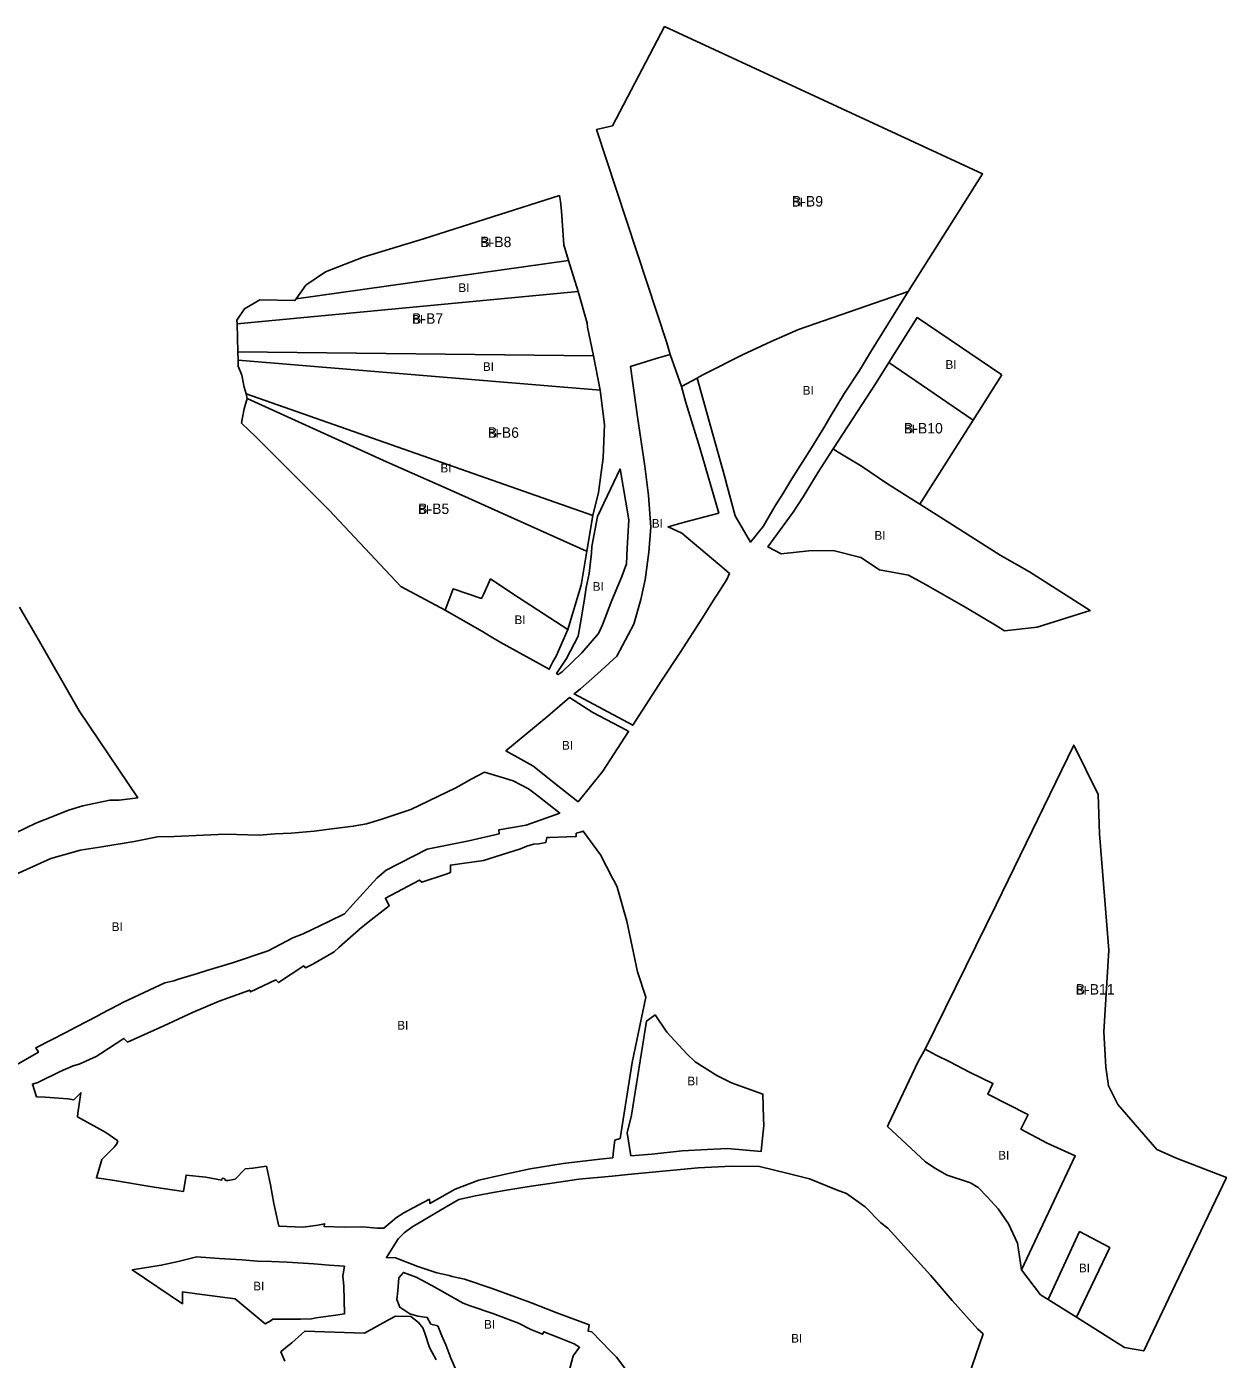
# Model space of a CAD drawing. Extents: x -532081 to -530154, y -1179372 to -1177675.
# Drawn here: x -530843 to -530154, y -1178440 to -1177675 of the extents above; entities that cross this region are included whole.
import ezdxf

# ---------------------------------------------------------------- set-up
doc = ezdxf.new("R2010")
doc.units = 0
for name, color, linetype in [('90040013', 7, 'Continuous'), ('90040023', 7, 'Continuous'), ('ID_navrh', 7, 'Continuous')]:
    doc.layers.add(name, color=color, linetype=linetype)

msp = doc.modelspace()

# ---------------------------------------------------------------- linework, layer by layer
at = {"layer": '90040013'}
for points in [[(-530526.69, -1177827.31), (-530722.54, -1177845.73), (-530722.6, -1177843.68), (-530718.37, -1177837.23), (-530709.55, -1177832.07), (-530689.34, -1177832.44), (-530688.56, -1177831.34), (-530532.17, -1177809.38)], [(-530420.51, -1177962.1), (-530427.66, -1177971.09), (-530436.58, -1177955.98), (-530441.05, -1177938.92), (-530442.44, -1177933.89), (-530450.53, -1177905.07), (-530458.33, -1177876.89), (-530457.17, -1177876.17), (-530454.3, -1177874.68), (-530431.86, -1177863.3), (-530415.76, -1177855.88), (-530400.19, -1177849), (-530337.11, -1177827.29), (-530358.71, -1177862.11), (-530365.16, -1177872.5), (-530373.77, -1177885.58), (-530381.89, -1177899.15), (-530385.09, -1177904.58), (-530392.72, -1177916.92), (-530404.03, -1177934.69), (-530409.22, -1177943.28), (-530413.51, -1177950.3)], [(-530283.32, -1177875.02), (-530299.85, -1177901.09), (-530348.29, -1177868.05), (-530332.03, -1177842.16)], [(-530517.77, -1177864.16), (-530514.06, -1177883.77), (-530721.96, -1177866.61), (-530722.09, -1177861.89)], [(-530478.55, -1178050.25), (-530495.32, -1178076.19), (-530529, -1178058.26), (-530527.39, -1178056.99), (-530525.33, -1178055.37), (-530515.59, -1178046.73), (-530504.42, -1178036.64), (-530494.66, -1178018.22), (-530490.7, -1178004.09), (-530488.92, -1177996.27), (-530488.25, -1177992.7), (-530486.02, -1177976.84), (-530484.86, -1177962.56), (-530486.25, -1177944.29), (-530488.45, -1177927.41), (-530489.14, -1177922.4), (-530492.61, -1177899.23), (-530496.53, -1177870.21), (-530481.9, -1177865.72), (-530473.8, -1177863.4), (-530467.3, -1177881.68), (-530464.84, -1177890.96), (-530456.71, -1177916.98), (-530445.9, -1177954.38), (-530465.57, -1177959.62), (-530474.98, -1177962.4), (-530467.09, -1177965.9), (-530442.82, -1177986.45), (-530439.7, -1177989.13), (-530441.26, -1177992.48), (-530447.05, -1178001.63), (-530447.92, -1178002.82), (-530455.3, -1178014.53), (-530468.16, -1178034.39)], [(-530518.2, -1177955.79), (-530521.7, -1177976.32), (-530521.84, -1177976.26), (-530599.09, -1177941.7), (-530636.79, -1177924.96), (-530716.72, -1177888.65), (-530717.29, -1177885.88)], [(-530305.43, -1177965.26), (-530284.27, -1177978.52), (-530267.44, -1177988.17), (-530232.58, -1178010.35), (-530263.11, -1178020), (-530281.81, -1178022), (-530286.1, -1178019.27), (-530304.04, -1178008.7), (-530326.86, -1177995.6), (-530337, -1177990.12), (-530353.57, -1177986.99), (-530364.3, -1177979.95), (-530380.29, -1177975.84), (-530394.13, -1177976.04), (-530410.12, -1177977.8), (-530417.72, -1177973.89), (-530403.28, -1177953.92), (-530397.51, -1177945), (-530388.86, -1177931.01), (-530380.2, -1177917.5), (-530378.27, -1177918.87), (-530363.91, -1177927.5), (-530349.67, -1177937.28), (-530335, -1177946.44), (-530330.45, -1177949.34)], [(-530535.84, -1178045.55), (-530538.18, -1178047.15), (-530539.04, -1178046.51), (-530533.34, -1178037.99), (-530526.74, -1178025.1), (-530525.56, -1178018.51), (-530523.19, -1178005.02), (-530522.14, -1177997.17), (-530520.32, -1177989.19), (-530519.04, -1177977.52), (-530518.82, -1177973.51), (-530515.49, -1177956.39), (-530502.63, -1177929.03), (-530497.53, -1177958.39), (-530498.48, -1177974.59), (-530498.93, -1177983.57), (-530501.67, -1177990.89), (-530507.53, -1178005.02), (-530512.76, -1178018.51), (-530515.07, -1178023.53), (-530524.49, -1178034.66)], [(-530564.12, -1178000.77), (-530532.63, -1178021.21), (-530539.39, -1178036.59), (-530541.13, -1178039.86), (-530543.23, -1178044.06), (-530571.38, -1178028.54), (-530577.55, -1178024.92), (-530581.65, -1178022.35), (-530590.11, -1178017.57), (-530602.97, -1178010.16), (-530598.51, -1177997.98), (-530582.15, -1178003.45), (-530580.91, -1178000.72), (-530576.94, -1177992.26)], [(-530512.53, -1178102.63), (-530526.69, -1178120.12), (-530536.63, -1178112.26), (-530552.77, -1178099.51), (-530568.14, -1178090.84), (-530544, -1178071.07), (-530531.7, -1178060.34), (-530518.29, -1178068.83), (-530498.95, -1178079.05), (-530497.7, -1178079.72)], [(-530505.6, -1178166.34), (-530504.31, -1178169.13), (-530498.75, -1178188.63), (-530492.64, -1178217.79), (-530487.83, -1178232.28), (-530495.59, -1178269.85), (-530502.57, -1178313.36), (-530505.56, -1178314.36), (-530506.31, -1178320.36), (-530506.83, -1178324.53), (-530514.29, -1178325.36), (-530535.23, -1178327.86), (-530554.18, -1178330.86), (-530570.13, -1178334.37), (-530583.63, -1178337.37), (-530597.26, -1178342.58), (-530611.92, -1178350.7), (-530612.1, -1178348.28), (-530618.61, -1178351.63), (-530626.79, -1178356.15), (-530631, -1178358.77), (-530638.26, -1178364.84), (-530642.17, -1178364.84), (-530650.48, -1178364.15), (-530660.87, -1178364.28), (-530672.46, -1178364.02), (-530672.33, -1178362.41), (-530676.14, -1178363.11), (-530684.55, -1178364.36), (-530698.61, -1178363.74), (-530698.94, -1178361.96), (-530701.46, -1178350.73), (-530703.26, -1178340.01), (-530705.74, -1178329.32), (-530713.4, -1178330.41), (-530717.88, -1178330.82), (-530723.69, -1178336.85), (-530727.58, -1178337.48), (-530729.09, -1178337.48), (-530729.96, -1178336.47), (-530731.09, -1178336.22), (-530731.35, -1178337.35), (-530740.56, -1178335.56), (-530751.78, -1178334.47), (-530753.32, -1178343.95), (-530770.16, -1178341.36), (-530794.04, -1178337.4), (-530803.31, -1178336.02), (-530800.22, -1178325.51), (-530793.18, -1178318.44), (-530791.5, -1178316.56), (-530791.05, -1178314.8), (-530797.82, -1178310), (-530801.4, -1178308.03), (-530814.14, -1178301.04), (-530813.97, -1178298.97), (-530812.19, -1178287.22), (-530816.3, -1178291.26), (-530819.74, -1178290.7), (-530832.81, -1178289.76), (-530837.7, -1178289.49), (-530840.12, -1178282.23), (-530836.98, -1178281.32), (-530824.17, -1178274.97), (-530816.66, -1178271.63), (-530813.15, -1178270.75), (-530803.54, -1178266.32), (-530800.84, -1178264.72), (-530787.52, -1178255.98), (-530785.38, -1178258.13), (-530773.91, -1178252.91), (-530764.58, -1178248.76), (-530748.05, -1178241.09), (-530732.85, -1178234.6), (-530715.28, -1178228.28), (-530714.78, -1178229.28), (-530700.19, -1178222.29), (-530698.7, -1178223.96), (-530684.28, -1178214.31), (-530683.28, -1178215.48), (-530679.04, -1178213.37), (-530666.8, -1178206.33), (-530663.9, -1178203.53), (-530651.18, -1178192.35), (-530645.46, -1178187.88), (-530635.19, -1178179.84), (-530637.33, -1178175.53), (-530617.69, -1178165.13), (-530616.35, -1178166.36), (-530602.55, -1178161.64), (-530599.89, -1178160.73), (-530600.01, -1178156.45), (-530581.1, -1178153.88), (-530559.81, -1178147.13), (-530556.2, -1178145.56), (-530552.4, -1178144.5), (-530549.29, -1178144.3), (-530545.19, -1178143.44), (-530544.68, -1178140.71), (-530542.9, -1178140.64), (-530533.15, -1178140.29), (-530527.86, -1178140.1), (-530527.74, -1178138.2), (-530525.6, -1178137.56), (-530523.75, -1178137), (-530513.75, -1178150.56), (-530506.9, -1178163.93)], [(-530421.18, -1178316.94), (-530421.63, -1178320.96), (-530440.96, -1178319.17), (-530452.52, -1178319.84), (-530466.92, -1178320.61), (-530484.38, -1178322.36), (-530496.34, -1178323.36), (-530498.58, -1178310.11), (-530496.09, -1178300.11), (-530487.33, -1178246.05), (-530482.46, -1178242.5), (-530475.79, -1178252.34), (-530464.31, -1178264.78), (-530459.41, -1178269.46), (-530446.96, -1178277.26), (-530438.52, -1178281.5), (-530420.52, -1178287.96), (-530420.29, -1178302.01), (-530420.08, -1178305.91)], [(-530241.24, -1178323.4), (-530271.98, -1178388.9), (-530274.27, -1178373.6), (-530279.6, -1178362.39), (-530285.45, -1178353.72), (-530291.55, -1178347.09), (-530296.88, -1178341.49), (-530301.35, -1178338.86), (-530314.76, -1178334.53), (-530321.91, -1178330.48), (-530327.14, -1178326.88), (-530348.95, -1178306.5), (-530348.36, -1178305.25), (-530331.32, -1178269.19), (-530327.44, -1178262.14), (-530321.16, -1178265.59), (-530313.24, -1178269.49), (-530305.92, -1178273.23), (-530301.89, -1178275.33), (-530288.44, -1178281.93), (-530291.42, -1178287.96), (-530268.5, -1178299.64), (-530268.3, -1178299.74), (-530272.39, -1178308.05), (-530257.28, -1178316.15)], [(-530221.35, -1178376.08), (-530240.56, -1178416.04), (-530256.77, -1178405.93), (-530238.68, -1178366.84)], [(-530661.31, -1178398.14), (-530660.84, -1178414.08), (-530665.91, -1178414.92), (-530670.24, -1178415.44), (-530677.08, -1178416.31), (-530679.79, -1178416.92), (-530686.05, -1178417.21), (-530702, -1178417.06), (-530703.51, -1178418.23), (-530706.38, -1178419.91), (-530723.56, -1178405.5), (-530745.7, -1178402.52), (-530753.85, -1178401.43), (-530753.85, -1178408.32), (-530782.71, -1178388.88), (-530766.13, -1178386.18), (-530756.39, -1178384.1), (-530745.62, -1178381.4), (-530732.77, -1178382.23), (-530719.72, -1178383.06), (-530710.81, -1178383.89), (-530702.73, -1178384.1), (-530693.82, -1178384.52), (-530678.48, -1178385.35), (-530669.68, -1178386.08), (-530660.87, -1178386.8), (-530661.78, -1178392.19)]]:
    msp.add_lwpolyline(points, close=True, dxfattribs=at)
for points in [[(-530855.76, -1178164.5), (-530829.59, -1178152.67), (-530814.58, -1178148.58), (-530812.65, -1178147.93), (-530800.3, -1178145.92), (-530781.72, -1178142.92), (-530768.33, -1178140.31), (-530758.74, -1178140.11), (-530729.18, -1178138.71), (-530709.8, -1178139.31), (-530700.61, -1178138.51), (-530691.42, -1178138.11), (-530678.23, -1178137.11), (-530668.12, -1178135.67), (-530655.84, -1178134.22), (-530648.15, -1178132.71), (-530640.01, -1178130.4), (-530622.67, -1178124.55), (-530597.01, -1178112.12), (-530588.18, -1178107.13), (-530580.41, -1178103.2), (-530570.96, -1178105.98), (-530563.93, -1178108.21), (-530555.23, -1178112.67), (-530549.84, -1178116.65), (-530537.24, -1178126.6), (-530556.54, -1178133.54), (-530572.24, -1178136.34), (-530572.07, -1178138.57), (-530589.41, -1178142.47), (-530613.47, -1178147.44), (-530637, -1178159.33), (-530642.12, -1178163.74), (-530656.02, -1178179.13), (-530660.9, -1178184.38), (-530669.44, -1178188.76), (-530684.67, -1178196), (-530690.43, -1178198.2), (-530704.76, -1178205.72), (-530725.12, -1178212.58), (-530739.92, -1178217.03), (-530745.28, -1178218.64), (-530756.76, -1178222.22), (-530758.83, -1178222.86), (-530763.98, -1178224.12), (-530773.05, -1178228.27), (-530787.86, -1178235.15), (-530790.67, -1178236.64), (-530800.56, -1178241.96), (-530802.87, -1178243.21), (-530815.05, -1178249.54), (-530820.79, -1178252.53), (-530838.17, -1178261.32), (-530836.67, -1178263.93), (-530856.88, -1178275.56)], [(-530493.42, -1178453.9), (-530504.6, -1178439.02), (-530508.01, -1178435.6), (-530518.91, -1178424.44), (-530520.95, -1178423.98), (-530520.38, -1178420.33), (-530538.82, -1178413.5), (-530553.95, -1178407.53), (-530562.55, -1178404.61), (-530576.04, -1178399.59), (-530592.03, -1178394.15), (-530594.54, -1178393.6), (-530599, -1178392.7), (-530600.66, -1178391.99), (-530607.81, -1178390.55), (-530618.65, -1178386.91), (-530631.62, -1178382.03), (-530636.82, -1178381.78), (-530629.99, -1178371.06), (-530626.54, -1178367.67), (-530622.28, -1178364.38), (-530616.15, -1178360.69), (-530602.46, -1178352.62), (-530595.21, -1178348.41), (-530585.67, -1178346.29), (-530575.51, -1178344.35), (-530567.8, -1178343.12), (-530553.61, -1178340.84), (-530541.53, -1178339.08), (-530526.29, -1178336.8), (-530507.19, -1178335.04), (-530498.07, -1178334.03), (-530475.92, -1178332.01), (-530457.8, -1178330.32), (-530438.62, -1178329.34), (-530422.59, -1178329.47), (-530406.06, -1178333.49), (-530393.82, -1178336.67), (-530378.34, -1178342.84), (-530372.58, -1178345.03), (-530361.87, -1178352.6), (-530352.82, -1178361.77), (-530348.8, -1178364.96), (-530324.28, -1178391.92), (-530311.86, -1178406.49), (-530297.13, -1178422.95), (-530294.09, -1178425.6), (-530302.58, -1178450.15)], [(-530594.39, -1178451.84), (-530599.84, -1178439.46), (-530602.57, -1178431.91), (-530604.89, -1178426.68), (-530607.29, -1178420.89), (-530611.25, -1178419.93), (-530613.31, -1178416.17), (-530618.74, -1178415.38), (-530623.33, -1178414.13), (-530629.02, -1178410.27), (-530630.72, -1178405.94), (-530630.26, -1178400.85), (-530629.64, -1178393.43), (-530627.02, -1178390.34), (-530619.63, -1178392.97), (-530610.77, -1178397.82), (-530593.16, -1178407.79), (-530590.75, -1178408.67), (-530588.72, -1178409.4), (-530575.76, -1178413.85), (-530561.01, -1178419.37), (-530553.86, -1178423.11), (-530547.06, -1178425.81), (-530546.47, -1178424.34), (-530537.62, -1178427.86), (-530528.9, -1178431.32), (-530525.84, -1178433.27), (-530529.57, -1178438.26), (-530531.53, -1178445.39)], [(-530695.14, -1178441.21), (-530697.33, -1178435.88), (-530694.61, -1178433.49), (-530691.09, -1178430.8), (-530683.63, -1178424.02), (-530649.41, -1178425.15), (-530634.91, -1178417.1), (-530631.62, -1178415.35), (-530622.68, -1178415.71), (-530618.38, -1178419.1), (-530615.85, -1178422.21), (-530614.79, -1178425.2), (-530612.05, -1178433.34), (-530608.21, -1178440.48)]]:
    msp.add_lwpolyline(points, dxfattribs=at)
at = {"layer": '90040023'}
for points in [[(-530475.73, -1177856.68), (-530516.06, -1177734.32), (-530506.97, -1177732.09), (-530477.02, -1177675.19), (-530294.42, -1177759.74), (-530305.17, -1177776.72), (-530337.11, -1177827.29), (-530400.19, -1177849), (-530415.76, -1177855.88), (-530431.86, -1177863.3), (-530454.3, -1177874.68), (-530457.17, -1177876.17), (-530458.33, -1177876.89), (-530467.3, -1177881.68), (-530473.8, -1177863.4)], [(-530532.17, -1177809.38), (-530688.56, -1177831.34), (-530682.98, -1177823.5), (-530671.69, -1177815.88), (-530650.19, -1177807.6), (-530615.45, -1177796.93), (-530575.84, -1177784.37), (-530537.46, -1177772.19), (-530536.85, -1177775.56), (-530536.33, -1177781.1), (-530534.91, -1177800.42)], [(-530517.77, -1177864.16), (-530722.09, -1177861.89), (-530722.54, -1177845.73), (-530526.69, -1177827.31), (-530521.57, -1177845.43), (-530521.38, -1177847.62)], [(-530518.2, -1177955.79), (-530717.29, -1177885.88), (-530718.44, -1177882.21), (-530718.86, -1177880.22), (-530719.8, -1177875.18), (-530721.86, -1177870.04), (-530721.96, -1177866.61), (-530514.06, -1177883.77), (-530511.54, -1177903.62), (-530512.28, -1177922.73), (-530514.96, -1177942.64)], [(-530380.2, -1177917.5), (-530355.56, -1177879.64), (-530348.29, -1177868.05), (-530299.85, -1177901.09), (-530330.45, -1177949.34), (-530335, -1177946.44), (-530349.67, -1177937.28), (-530363.91, -1177927.5), (-530378.27, -1177918.87)], [(-530669.65, -1177952.73), (-530712.04, -1177910.46), (-530719.97, -1177902.75), (-530719.47, -1177899.52), (-530718.43, -1177894.56), (-530716.72, -1177888.65), (-530636.79, -1177924.96), (-530599.09, -1177941.7), (-530521.84, -1177976.26), (-530521.7, -1177976.32), (-530525.01, -1177995.73), (-530532.63, -1178021.21), (-530564.12, -1178000.77), (-530576.94, -1177992.26), (-530580.91, -1178000.72), (-530582.15, -1178003.45), (-530598.51, -1177997.98), (-530602.97, -1178010.16), (-530628.5, -1177996.49)], [(-530224.72, -1178252.13), (-530223.67, -1178272.52), (-530222.1, -1178283.2), (-530216.72, -1178294), (-530194.29, -1178319.8), (-530182.63, -1178324.9), (-530154.42, -1178335.79), (-530183.82, -1178397.49), (-530201.91, -1178435.37), (-530212.83, -1178433.33), (-530240.56, -1178416.04), (-530221.35, -1178376.08), (-530238.68, -1178366.84), (-530256.77, -1178405.93), (-530261.15, -1178403.2), (-530271.98, -1178388.9), (-530241.24, -1178323.4), (-530257.28, -1178316.15), (-530272.39, -1178308.05), (-530268.3, -1178299.74), (-530268.5, -1178299.64), (-530291.42, -1178287.96), (-530288.44, -1178281.93), (-530301.89, -1178275.33), (-530305.92, -1178273.23), (-530313.24, -1178269.49), (-530321.16, -1178265.59), (-530327.44, -1178262.14), (-530286.61, -1178179.35), (-530242.09, -1178087.57), (-530228.13, -1178116.05), (-530227.19, -1178138.6), (-530221.85, -1178205.36)]]:
    msp.add_lwpolyline(points, close=True, dxfattribs=at)
msp.add_lwpolyline([(-530847.41, -1178008.47), (-530836.83, -1178026.85), (-530813.19, -1178067.91), (-530779.61, -1178117.88), (-530790.3, -1178119.29), (-530795.55, -1178119.28), (-530801.25, -1178120.46), (-530811.08, -1178122.44), (-530819.34, -1178125), (-530827.4, -1178128.15), (-530838.02, -1178132.49), (-530850.01, -1178138.21)], dxfattribs=at)

# ---------------------------------------------------------------- texts
at = {"layer": '90040013'}
msp.add_text('BI', height=5, dxfattribs=at).set_placement((-530595.43, -1177827.55))
for rotation, p in [(360, (-530315.7, -1177871.63)), (0, (-530581.35, -1177872.83)), (0, (-530397.72, -1177886.46)), (360, (-530605.73, -1177931.1)), (360, (-530484.35, -1177962.85)), (360, (-530356.49, -1177969.75)), (360, (-530518.28, -1177999.05)), (0, (-530563.2, -1178018.16)), (360, (-530535.95, -1178090.23)), (0, (-530794.51, -1178194.33)), (0, (-530630.55, -1178250.92)), (0, (-530463.92, -1178282.93)), (360, (-530285.42, -1178325.52)), (0, (-530239.06, -1178390.28)), (0, (-530713.23, -1178400.65)), (360, (-530580.68, -1178422.62)), (0, (-530404.35, -1178430.62))]:
    msp.add_text('BI', height=5, rotation=rotation, dxfattribs=at).set_placement(p)
at = {"layer": '90040023'}
for rotation, p in [(0, (-530403.89, -1177778.44)), (360, (-530582.85, -1177801.77)), (0, (-530622.04, -1177845.74)), (0, (-530339.57, -1177908.7)), (360, (-530578.51, -1177911.2)), (360, (-530240.93, -1178230.82))]:
    msp.add_text('BI', height=5, rotation=rotation, dxfattribs=at).set_placement(p)
msp.add_text('BI', height=5, dxfattribs=at).set_placement((-530618.55, -1177954.93))
at = {"layer": 'ID_navrh'}
for s, rotation, p in [('B-B9', 0, (-530403.89, -1177778.44)), ('B-B8', 0, (-530582.85, -1177801.77)), ('B-B7', 0, (-530622.04, -1177845.74)), ('B-B6', 360, (-530578.51, -1177911.2)), ('B-B5', 360, (-530618.55, -1177954.93)), ('B-B11', 360, (-530240.93, -1178230.82))]:
    msp.add_text(s, height=6, rotation=rotation, dxfattribs=at).set_placement(p)
msp.add_text('B-B10', height=6, dxfattribs=at).set_placement((-530339.57, -1177908.7))

doc.saveas('drawing.dxf')
